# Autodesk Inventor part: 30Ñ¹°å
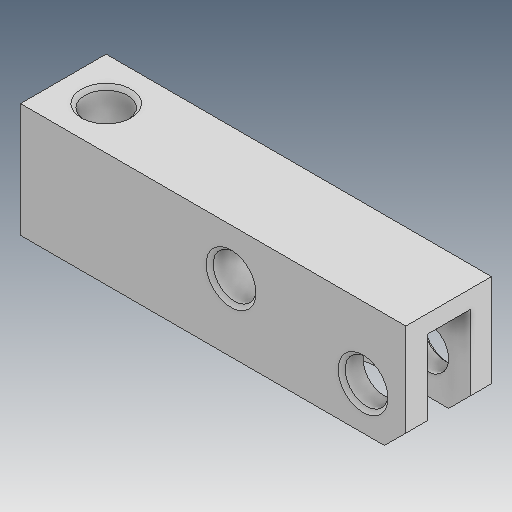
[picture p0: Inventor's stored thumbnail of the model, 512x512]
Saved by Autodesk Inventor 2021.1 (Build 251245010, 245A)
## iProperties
Created: 2019-04
Part Number: 30Ñ¹°å
Material: Ogólny
Document SubType Name: Modeling
Designer: user
Density: 1 g/cm^3
Appearance: Domyślna
Author: user
Revision Number: ÈÎºÎ
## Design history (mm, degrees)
feature "ÊäÈë1"
node "Bryła1"
